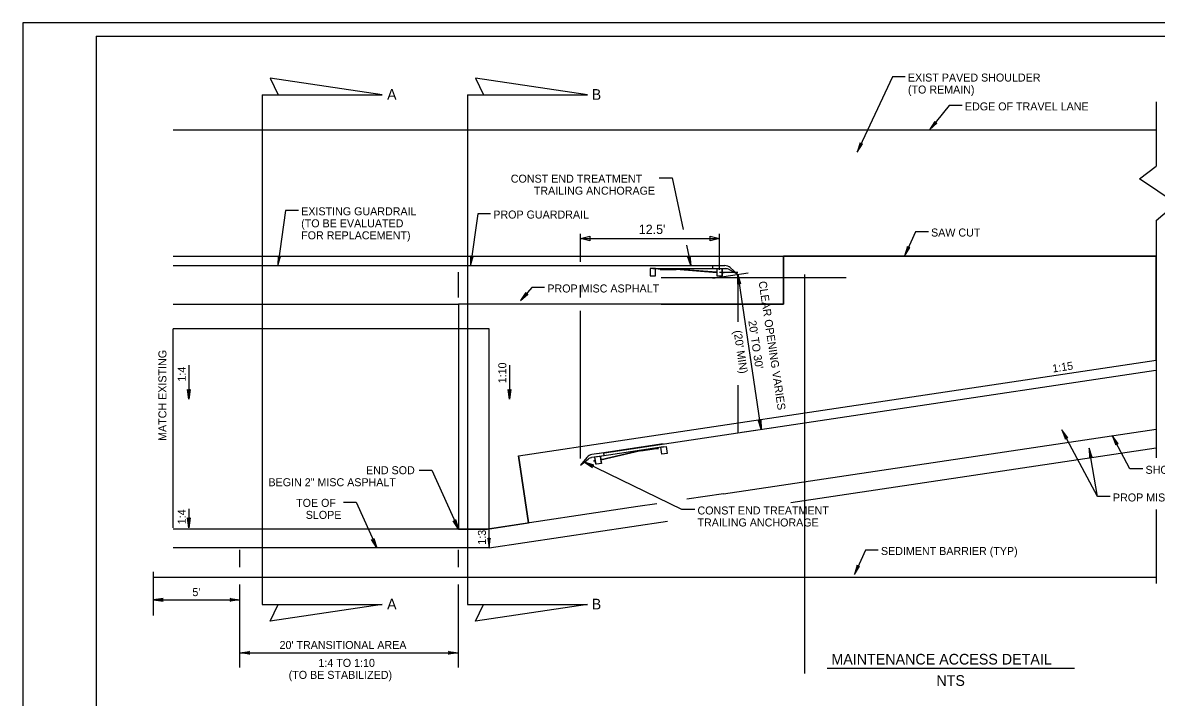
# Model space of a CAD drawing. Extents: x 96794 to 96959, y 32203 to 32309.
# Drawn here: x 96793.8 to 96878.8, y 32258 to 32308.6 of the extents above; entities that cross this region are included whole.
import ezdxf

# ---------------------------------------------------------------- set-up
doc = ezdxf.new("R2010")
doc.units = 0
for name, color, linetype in [('AsphaltMisc', 7, 'Continuous'), ('Attenuator', 7, 'Continuous'), ('DimLines_dp', 7, 'Continuous'), ('EOP', 7, 'Continuous'), ('GuardrailEndAch', 7, 'Continuous'), ('GuardrailRt', 7, 'Continuous'), ('LeaderLine_dp', 7, 'Continuous'), ('Nonplot 6', 7, 'Continuous'), ('PlotBorder_dp', 7, 'Continuous'), ('SawCuts', 7, 'Continuous'), ('SheetBorder_dp', 7, 'Continuous'), ('ShldrPaved', 7, 'Continuous'), ('SiltFence', 7, 'Continuous'), ('Slopes_px', 7, 'Continuous'), ('TextMisc', 7, 'Continuous'), ('TextTitle', 7, 'Continuous')]:
    doc.layers.add(name, color=color, linetype=linetype)

msp = doc.modelspace()

# ---------------------------------------------------------------- linework, layer by layer
at = {"layer": 'AsphaltMisc'}
for p, q in [((96805.09, 32291.064), (96827.163, 32291.064)), ((96850.867, 32287.464), (96850.867, 32291.064)), ((96878.815, 32291.064), (96850.867, 32291.064)), ((96850.867, 32291.064), (96850.867, 32287.464)), ((96878.815, 32283.251), (96878.815, 32291.064)), ((96826.477, 32287.964), (96826.477, 32289.844)), ((96847.425, 32289.682), (96847.425, 32286.142)), ((96805.09, 32287.464), (96826.477, 32287.464)), ((96841.683, 32287.464), (96850.867, 32287.464)), ((96850.867, 32287.464), (96841.683, 32287.464)), ((96805.09, 32270.697), (96805.09, 32285.601)), ((96859.982, 32280.435), (96878.815, 32283.251)), ((96859.982, 32280.435), (96878.815, 32283.251)), ((96847.425, 32281.395), (96847.425, 32277.818)), ((96838.964, 32277.293), (96859.982, 32280.435)), ((96859.982, 32280.435), (96859.982, 32280.435)), ((96846.356, 32273.241), (96878.815, 32278.094)), ((96830.981, 32276.099), (96831.735, 32271.056)), ((96846.356, 32273.241), (96843.595, 32272.829)), ((96839.945, 32272.283), (96828.669, 32270.597)), ((96841.37, 32272.496), (96839.945, 32272.283)), ((96828.669, 32270.597), (96805.09, 32270.597))]:
    msp.add_line(p, q, dxfattribs=at)
for points in [[(96841.683, 32287.464), (96826.477, 32287.464), (96826.477, 32270.597)], [(96828.773, 32269.197), (96828.773, 32285.601), (96805.09, 32285.601)], [(96826.477, 32270.597), (96828.669, 32270.597), (96831.735, 32271.056), (96830.981, 32276.099), (96838.964, 32277.293)]]:
    msp.add_lwpolyline(points, dxfattribs=at)
at = {"layer": 'Attenuator'}
msp.add_line((96841.683, 32289.464), (96855.559, 32289.464), dxfattribs=at)
at = {"layer": 'DimLines_dp'}
for p, q in [((96811.769, 32303.143), (96811.769, 32264.949)), ((96811.769, 32303.143), (96820.769, 32303.143)), ((96827.163, 32303.143), (96836.163, 32303.143)), ((96827.163, 32303.143), (96827.163, 32264.949)), ((96878.815, 32302.629), (96878.815, 32297.806)), ((96877.562, 32296.845), (96878.815, 32297.806)), ((96880.291, 32295.003), (96877.562, 32296.845)), ((96878.815, 32293.721), (96880.291, 32295.003)), ((96878.815, 32293.721), (96878.815, 32275.937)), ((96835.638, 32290.619), (96835.638, 32292.728)), ((96846.065, 32290.032), (96846.065, 32292.728)), ((96835.638, 32292.378), (96846.065, 32292.378)), ((96845.551, 32289.402), (96848.216, 32289.8)), ((96847.425, 32289.682), (96849.16, 32278.077)), ((96835.638, 32287.964), (96835.638, 32288.869)), ((96835.638, 32275.886), (96835.638, 32286.964)), ((96806.269, 32282.876), (96806.269, 32280.328)), ((96830.303, 32282.876), (96830.303, 32280.328)), ((96806.269, 32281.725), (96806.269, 32280.328)), ((96830.303, 32281.725), (96830.303, 32280.328)), ((96847.728, 32277.863), (96849.963, 32278.197)), ((96806.269, 32272.113), (96806.269, 32270.697)), ((96806.269, 32272.094), (96806.269, 32270.697)), ((96878.815, 32272.066), (96878.815, 32266.519)), ((96810.09, 32267.739), (96810.09, 32269.047)), ((96826.477, 32267.739), (96826.477, 32269.047)), ((96803.605, 32264.113), (96803.605, 32267.396)), ((96810.09, 32260.225), (96810.09, 32266.447)), ((96826.477, 32260.225), (96826.477, 32266.447)), ((96803.605, 32265.29), (96810.09, 32265.29)), ((96811.769, 32264.949), (96820.769, 32264.949)), ((96827.163, 32264.949), (96836.163, 32264.949)), ((96810.09, 32261.327), (96826.477, 32261.327)), ((96854.128, 32260.169), (96872.69, 32260.169))]:
    msp.add_line(p, q, dxfattribs=at)
for points in [[(96836.338, 32292.203), (96835.638, 32292.378), (96836.338, 32292.553)], [(96845.365, 32292.553), (96846.065, 32292.378), (96845.365, 32292.203)]]:
    msp.add_lwpolyline(points, close=True, dxfattribs=at)
for points in [[(96847.503, 32289.159), (96847.439, 32288.943), (96847.425, 32289.682), (96847.628, 32288.971), (96847.503, 32289.159)], [(96806.269, 32280.858), (96806.364, 32281.062), (96806.269, 32280.328), (96806.173, 32281.062), (96806.269, 32280.858)], [(96806.269, 32280.858), (96806.173, 32281.062), (96806.269, 32280.328), (96806.364, 32281.062), (96806.269, 32280.858)], [(96830.303, 32280.858), (96830.399, 32281.062), (96830.303, 32280.328), (96830.208, 32281.062), (96830.303, 32280.858)], [(96830.303, 32280.858), (96830.208, 32281.062), (96830.303, 32280.328), (96830.399, 32281.062), (96830.303, 32280.858)], [(96849.093, 32278.602), (96849.157, 32278.818), (96849.171, 32278.079), (96848.968, 32278.79), (96849.093, 32278.602)], [(96806.269, 32271.227), (96806.364, 32271.43), (96806.269, 32270.697), (96806.173, 32271.43), (96806.269, 32271.227)], [(96806.269, 32271.227), (96806.173, 32271.43), (96806.269, 32270.697), (96806.364, 32271.43), (96806.269, 32271.227)], [(96828.773, 32269.727), (96828.678, 32269.93), (96828.773, 32269.197), (96828.869, 32269.93), (96828.773, 32269.727)], [(96804.134, 32265.29), (96804.338, 32265.386), (96803.605, 32265.29), (96804.338, 32265.195), (96804.134, 32265.29)], [(96809.561, 32265.29), (96809.357, 32265.386), (96810.09, 32265.29), (96809.357, 32265.195), (96809.561, 32265.29)], [(96810.619, 32261.327), (96810.823, 32261.232), (96810.09, 32261.327), (96810.823, 32261.423), (96810.619, 32261.327)], [(96825.948, 32261.327), (96825.744, 32261.423), (96826.477, 32261.327), (96825.744, 32261.232), (96825.948, 32261.327)]]:
    msp.add_lwpolyline(points, dxfattribs=at)
at = {"layer": 'EOP'}
msp.add_line((96805.09, 32300.524), (96878.815, 32300.524), dxfattribs=at)
at = {"layer": 'GuardrailEndAch'}
for p, q in [((96841.267, 32290.119), (96840.867, 32290.119)), ((96840.867, 32290.119), (96840.867, 32289.586)), ((96841.067, 32290.344), (96846.067, 32290.344)), ((96841.067, 32290.119), (96846.067, 32290.119)), ((96841.267, 32289.586), (96841.267, 32290.119)), ((96841.601, 32290.103), (96841.467, 32290.103)), ((96841.467, 32290.069), (96841.467, 32290.103)), ((96841.601, 32290.069), (96841.467, 32290.069)), ((96841.601, 32290.119), (96841.601, 32290.053)), ((96842.799, 32290.069), (96845.867, 32289.836)), ((96842.801, 32290.119), (96842.801, 32290.053)), ((96842.802, 32290.103), (96845.867, 32289.869)), ((96845.558, 32290.349), (96846.459, 32290.349)), ((96845.558, 32290.119), (96845.558, 32290.349)), ((96845.558, 32290.119), (96846.523, 32290.119)), ((96845.854, 32290.119), (96845.854, 32289.87)), ((96845.867, 32290.119), (96845.867, 32289.586)), ((96845.867, 32290.119), (96846.267, 32290.119)), ((96846.267, 32289.586), (96846.267, 32290.119)), ((96846.267, 32290.119), (96846.281, 32290.119)), ((96846.281, 32289.586), (96846.281, 32290.119)), ((96846.863, 32290.193), (96847.425, 32289.682)), ((96840.867, 32289.586), (96841.267, 32289.586)), ((96841.601, 32290.053), (96842.801, 32290.053)), ((96845.854, 32289.837), (96845.854, 32289.573)), ((96845.854, 32289.573), (96846.201, 32289.573)), ((96845.867, 32289.586), (96846.267, 32289.586)), ((96846.201, 32289.573), (96846.201, 32289.586)), ((96846.267, 32289.586), (96846.281, 32289.586)), ((96846.281, 32289.856), (96846.401, 32289.856)), ((96846.281, 32289.823), (96846.401, 32289.823)), ((96846.401, 32289.823), (96846.401, 32289.856)), ((96847.425, 32289.682), (96846.789, 32290.048)), ((96841.828, 32276.981), (96836.883, 32276.242)), ((96841.861, 32276.758), (96836.916, 32276.019)), ((96840.148, 32276.485), (96837.151, 32275.801)), ((96840.147, 32276.502), (96840.156, 32276.436)), ((96841.343, 32276.614), (96840.156, 32276.436)), ((96841.333, 32276.679), (96841.343, 32276.614)), ((96841.336, 32276.663), (96841.468, 32276.683)), ((96841.341, 32276.63), (96841.473, 32276.65)), ((96841.473, 32276.65), (96841.468, 32276.683)), ((96841.663, 32276.729), (96842.059, 32276.788)), ((96841.742, 32276.201), (96841.663, 32276.729)), ((96842.059, 32276.788), (96842.137, 32276.26)), ((96836.118, 32275.974), (96835.638, 32275.386)), ((96835.638, 32275.386), (96836.213, 32275.842)), ((96837.42, 32276.094), (96836.465, 32275.952)), ((96837.386, 32276.321), (96836.494, 32276.188)), ((96836.744, 32275.727), (96836.625, 32275.71)), ((96836.63, 32275.677), (96836.625, 32275.71)), ((96836.749, 32275.694), (96836.63, 32275.677)), ((96836.718, 32275.989), (96836.705, 32275.987)), ((96836.784, 32275.46), (96836.705, 32275.987)), ((96837.114, 32276.049), (96836.718, 32275.989)), ((96836.797, 32275.462), (96836.718, 32275.989)), ((96837.114, 32276.049), (96837.192, 32275.521)), ((96837.127, 32276.051), (96837.164, 32275.804)), ((96840.155, 32276.453), (96837.155, 32275.768)), ((96837.169, 32275.771), (96837.208, 32275.51)), ((96837.42, 32276.094), (96837.386, 32276.321)), ((96842.137, 32276.26), (96841.742, 32276.201)), ((96836.797, 32275.462), (96836.784, 32275.46)), ((96837.192, 32275.521), (96836.797, 32275.462)), ((96836.865, 32275.459), (96836.863, 32275.472)), ((96837.208, 32275.51), (96836.865, 32275.459))]:
    msp.add_line(p, q, dxfattribs=at)
for centre, radius, start, end in [((96846.459, 32289.749), 0.6, 47.72631, 90), ((96846.523, 32289.586), 0.533, 60.05647, 90), ((96836.583, 32275.594), 0.6, 98.50276, 140.77645), ((96836.544, 32275.424), 0.533, 98.50276, 128.44629)]:
    msp.add_arc(centre, radius, start, end, dxfattribs=at)
at = {"layer": 'GuardrailRt'}
for p, q in [((96805.09, 32290.344), (96827.163, 32290.344)), ((96827.163, 32290.344), (96841.067, 32290.344)), ((96837.425, 32276.323), (96878.78, 32282.505))]:
    msp.add_line(p, q, dxfattribs=at)
at = {"layer": 'LeaderLine_dp'}
for p, q in [((96820.769, 32303.143), (96812.369, 32304.403)), ((96812.369, 32304.403), (96812.969, 32303.143)), ((96836.163, 32303.143), (96827.763, 32304.403)), ((96827.763, 32304.403), (96828.363, 32303.143)), ((96812.969, 32303.143), (96820.769, 32303.143)), ((96828.363, 32303.143), (96836.163, 32303.143)), ((96823.53, 32275.02), (96824.497, 32275.02)), ((96824.497, 32275.02), (96826.477, 32270.597)), ((96820.769, 32264.949), (96812.369, 32263.689)), ((96812.369, 32263.689), (96812.969, 32264.949)), ((96812.969, 32264.949), (96820.769, 32264.949)), ((96836.163, 32264.949), (96827.763, 32263.689)), ((96827.763, 32263.689), (96828.363, 32264.949)), ((96828.363, 32264.949), (96836.163, 32264.949))]:
    msp.add_line(p, q, dxfattribs=at)
for points in [[(96859.985, 32304.5), (96859.019, 32304.5), (96856.385, 32298.84)], [(96864.259, 32302.341), (96863.292, 32302.341), (96861.812, 32300.524)], [(96862.147, 32300.935), (96862.201, 32301.153), (96861.812, 32300.524), (96862.35, 32301.031), (96862.147, 32300.935)], [(96856.608, 32299.321), (96856.607, 32299.546), (96856.385, 32298.84), (96856.781, 32299.464), (96856.608, 32299.321)], [(96841.543, 32296.924), (96842.51, 32296.924), (96843.328, 32293.042)], [(96814.483, 32294.478), (96813.516, 32294.478), (96812.943, 32290.344)], [(96828.891, 32294.236), (96827.924, 32294.236), (96827.384, 32290.344)], [(96861.718, 32292.886), (96860.752, 32292.886), (96859.936, 32291.064)], [(96843.574, 32291.875), (96843.897, 32290.344)], [(96860.153, 32291.548), (96860.148, 32291.773), (96859.936, 32291.064), (96860.323, 32291.694), (96860.153, 32291.548)], [(96813.015, 32290.869), (96812.949, 32291.084), (96812.943, 32290.344), (96813.139, 32291.057), (96813.015, 32290.869)], [(96827.457, 32290.869), (96827.39, 32291.084), (96827.384, 32290.344), (96827.58, 32291.057), (96827.457, 32290.869)], [(96843.787, 32290.863), (96843.839, 32291.081), (96843.897, 32290.344), (96843.651, 32291.042), (96843.787, 32290.863)], [(96831.979, 32288.693), (96831.13, 32287.723)], [(96832.946, 32288.693), (96831.979, 32288.693)], [(96831.479, 32288.122), (96831.541, 32288.338), (96831.13, 32287.723), (96831.685, 32288.212), (96831.479, 32288.122)], [(96875.36, 32273.031), (96874.393, 32273.031), (96871.74, 32278.04)], [(96871.988, 32277.572), (96872.168, 32277.437), (96871.74, 32278.04), (96871.998, 32277.347), (96871.988, 32277.572)], [(96877.803, 32275.104), (96876.836, 32275.104), (96875.514, 32277.6)], [(96875.762, 32277.132), (96875.942, 32276.997), (96875.514, 32277.6), (96875.772, 32276.908), (96875.762, 32277.132)], [(96875.36, 32273.031), (96874.393, 32273.031), (96873.782, 32276.672)], [(96873.87, 32276.15), (96873.998, 32275.965), (96873.782, 32276.672), (96873.808, 32275.934), (96873.87, 32276.15)], [(96836.402, 32275.382), (96836.626, 32275.379), (96835.925, 32275.614), (96836.542, 32275.207), (96836.402, 32275.382)], [(96844.204, 32272.057), (96843.237, 32272.057), (96835.926, 32275.614)], [(96817.848, 32272.625), (96818.815, 32272.625), (96820.35, 32269.197)], [(96826.26, 32271.081), (96826.265, 32271.305), (96826.477, 32270.597), (96826.09, 32271.227), (96826.26, 32271.081)], [(96820.133, 32269.681), (96820.138, 32269.905), (96820.35, 32269.197), (96819.963, 32269.827), (96820.133, 32269.681)], [(96857.962, 32269.019), (96856.995, 32269.019), (96856.179, 32267.197)], [(96856.396, 32267.681), (96856.391, 32267.905), (96856.179, 32267.197), (96856.566, 32267.827), (96856.396, 32267.681)]]:
    msp.add_lwpolyline(points, dxfattribs=at)
at = {"layer": 'Nonplot 6'}
msp.add_line((96852.425, 32289.682), (96852.425, 32259.781), dxfattribs=at)
at = {"layer": 'PlotBorder_dp'}
msp.add_lwpolyline([(96793.801, 32202.551), (96958.801, 32202.551), (96958.801, 32308.551), (96793.801, 32308.551)], close=True, dxfattribs=at)
at = {"layer": 'SawCuts'}
msp.add_line((96850.867, 32291.064), (96878.815, 32291.064), dxfattribs=at)
at = {"layer": 'SheetBorder_dp'}
for q in [(96799.301, 32203.551), (96953.301, 32307.551)]:
    msp.add_line((96799.301, 32307.551), q, dxfattribs=at)
at = {"layer": 'ShldrPaved'}
msp.add_line((96827.163, 32291.064), (96850.867, 32291.064), dxfattribs=at)
at = {"layer": 'SiltFence'}
msp.add_line((96878.815, 32266.972), (96803.605, 32266.972), dxfattribs=at)
at = {"layer": 'Slopes_px'}
for p, q in [((96851.41, 32272.581), (96878.815, 32276.678)), ((96828.773, 32269.197), (96842.17, 32271.2)), ((96828.773, 32269.197), (96805.09, 32269.197))]:
    msp.add_line(p, q, dxfattribs=at)
at = {"layer": 'TextMisc'}
msp.add_line((96846.065, 32289.85), (96847.425, 32289.85), dxfattribs=at)

# ---------------------------------------------------------------- texts
at = {"layer": 'DimLines_dp'}
for s, height, p in [("12.5'", 0.7, (96840.005, 32292.712)), ('MAINTENANCE ACCESS DETAIL', 0.8, (96854.448, 32260.448)), ('NTS', 0.8, (96862.321, 32258.848))]:
    msp.add_text(s, height=height, dxfattribs=at).set_placement(p)
at = {"layer": 'TextMisc'}
for s, p in [('EXIST PAVED SHOULDER', (96860.188, 32304.138)), ('(TO REMAIN)', (96860.188, 32303.238)), ('EDGE OF TRAVEL LANE', (96864.462, 32301.978)), ('CONST END TREATMENT', (96830.405, 32296.561)), ('TRAILING ANCHORAGE', (96832.13, 32295.661)), ('EXISTING GUARDRAIL', (96814.686, 32294.115)), ('PROP GUARDRAIL', (96829.094, 32293.873)), ('(TO BE EVALUATED', (96814.686, 32293.215)), ('FOR REPLACEMENT)', (96814.686, 32292.315)), ('SAW CUT', (96861.921, 32292.524)), ('PROP MISC ASPHALT', (96833.149, 32288.331)), ('END SOD', (96819.548, 32274.71)), ('SHOULDER BREAK LINE', (96878.006, 32274.741)), ('BEGIN 2" MISC ASPHALT', (96812.233, 32273.81)), ('PROP MISC ASPHALT', (96875.562, 32272.668)), ('TOE OF', (96814.306, 32272.263)), ('CONST END TREATMENT', (96844.406, 32271.694)), ('SLOPE', (96815.029, 32271.363)), ('TRAILING ANCHORAGE', (96844.406, 32270.794)), ('SEDIMENT BARRIER (TYP)', (96858.164, 32268.656)), ("5'", (96806.527, 32265.575)), ("20' TRANSITIONAL AREA", (96813.065, 32261.612)), ('1:4 TO 1:10', (96815.98, 32260.272)), ('(TO BE STABILIZED)', (96813.749, 32259.372))]:
    msp.add_text(s, height=0.6, dxfattribs=at).set_placement(p)
for s, rotation, p in [('CLEAR OPENING VARIES', 278.50276, (96848.988, 32289.139)), ("20' TO 30'", 278.50276, (96848.216, 32286.191)), ("(20' MIN)", 278.50276, (96847.112, 32285.456)), ('MATCH EXISTING', 90, (96804.58, 32277.207)), ('1:4', 90, (96806.035, 32281.654)), ('1:10', 90, (96830.069, 32281.524)), ('1:15', 8.50276, (96871.062, 32282.33)), ('1:4', 90, (96806.035, 32270.958)), ('1:3', 90, (96828.54, 32269.428))]:
    msp.add_text(s, height=0.6, rotation=rotation, dxfattribs=at).set_placement(p)
at = {"layer": 'TextTitle'}
for s, p in [('A', (96821.128, 32302.772)), ('B', (96836.475, 32302.772)), ('A', (96821.128, 32264.578)), ('B', (96836.475, 32264.578))]:
    msp.add_text(s, height=0.8, dxfattribs=at).set_placement(p)

doc.saveas('drawing.dxf')
